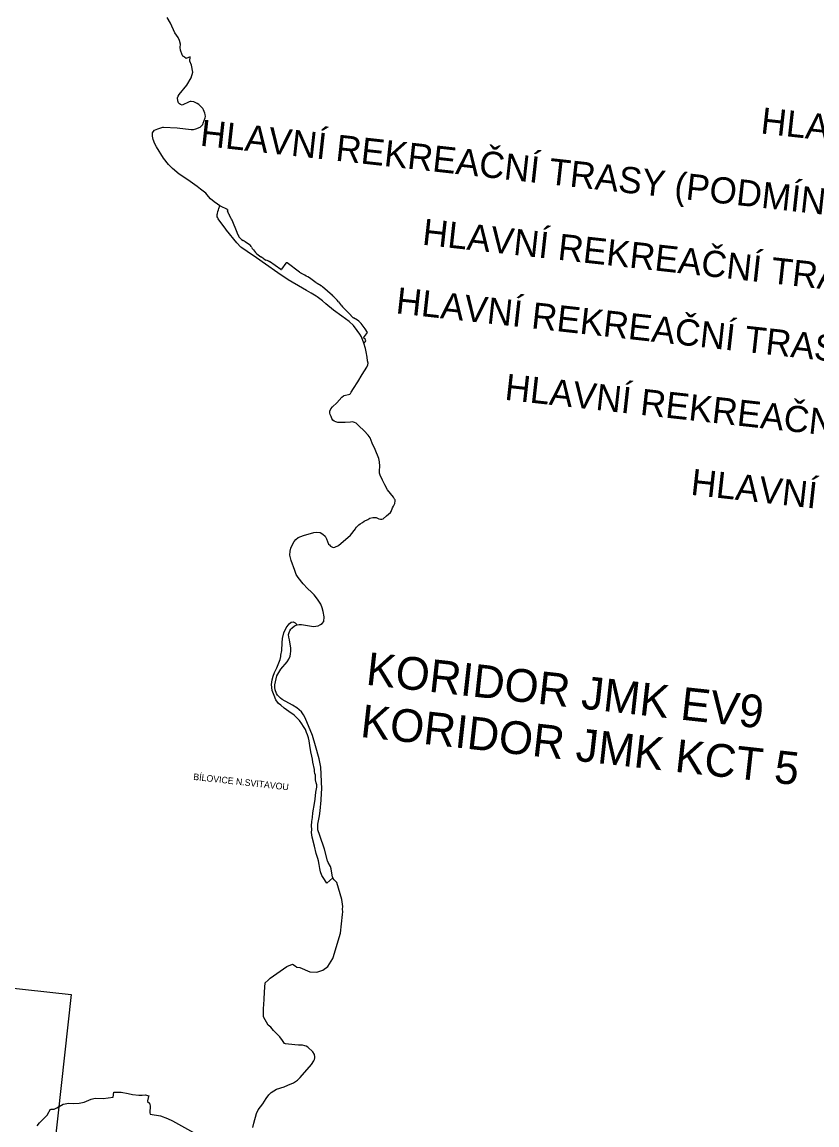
# Model space of a CAD drawing. Extents: x -678204 to -526855, y -1228851 to -1110393.
# Drawn here: x -595642 to -588360, y -1157650 to -1147551 of the extents above; entities that cross this region are included whole.
import ezdxf

# ---------------------------------------------------------------- set-up
doc = ezdxf.new("R2010")
doc.units = 0
for name, color, linetype in [('00_n_cyklo popisy', 7, 'Continuous'), ('00_n_cyklo popisy detaily', 7, 'Continuous'), ('00_n_cyklo prujezdne podminecne rekreacni vedlejsi', 7, 'Continuous'), ('00_n_cyklo prujezdne rekreacni hlavni', 7, 'Continuous'), ('00_n_cyklo studie rekreacni vedlejsi', 7, 'Continuous'), ('00_n_cyklo trasovani rekreacni hlavni', 7, 'Continuous'), ('00_n_cyklo trasovani rekreacni vedlejsi', 7, 'Continuous'), ('00_n_legenda popisy', 7, 'Continuous'), ('_HELP', 7, 'Continuous')]:
    doc.layers.add(name, color=color, linetype=linetype)

msp = doc.modelspace()

# ---------------------------------------------------------------- linework, layer by layer
at = {"layer": '00_n_cyklo prujezdne podminecne rekreacni vedlejsi'}
msp.add_lwpolyline([(-592796, -1155387), (-592849, -1155435), (-592855, -1155427), (-592878, -1155393), (-592894, -1155365), (-592907, -1155332), (-592915, -1155302), (-592920, -1155265), (-592925, -1155231), (-592932, -1155210), (-592947, -1155163), (-592962, -1155097), (-592983, -1155015), (-592990, -1154971), (-592988, -1154944), (-592989, -1154910), (-592987, -1154872), (-592982, -1154835), (-592977, -1154792), (-592962, -1154707), (-592958, -1154667), (-592951, -1154603), (-592940, -1154558), (-592941, -1154535), (-592946, -1154518), (-592952, -1154490), (-592953, -1154466), (-592955, -1154446), (-592960, -1154432), (-592962, -1154414), (-592964, -1154396), (-592978, -1154329), (-592982, -1154301), (-592987, -1154273), (-592995, -1154232), (-593006, -1154175), (-593012, -1154134), (-593018, -1154106), (-593027, -1154079), (-593037, -1154055), (-593046, -1154030), (-593062, -1154001), (-593079, -1153976), (-593099, -1153948), (-593114, -1153931), (-593148, -1153899), (-593198, -1153865), (-593240, -1153834), (-593272, -1153807), (-593291, -1153792), (-593316, -1153756), (-593332, -1153719), (-593349, -1153671), (-593356, -1153618), (-593350, -1153574), (-593341, -1153542), (-593330, -1153508), (-593309, -1153465), (-593278, -1153387), (-593270, -1153359), (-593270, -1153347), (-593263, -1153307), (-593260, -1153234), (-593256, -1153195), (-593243, -1153144), (-593222, -1153097), (-593196, -1153062), (-593177, -1153046), (-593158, -1153043), (-593141, -1153051), (-593132, -1153062), (-593128, -1153074)], dxfattribs=at)
at = {"layer": '00_n_cyklo prujezdne rekreacni hlavni'}
for points in [[(-593529, -1157674), (-593517, -1157635), (-593493, -1157546), (-593479, -1157511), (-593436, -1157456), (-593406, -1157409), (-593380, -1157374), (-593369, -1157361), (-593359, -1157353), (-593312, -1157323), (-593240, -1157300), (-593207, -1157287), (-593155, -1157263), (-593119, -1157240), (-593094, -1157216), (-592991, -1157097), (-592968, -1157063), (-592962, -1157051), (-592959, -1157036), (-592959, -1157026), (-592964, -1157005), (-592979, -1156981), (-593024, -1156939), (-593038, -1156930), (-593051, -1156925), (-593073, -1156920), (-593110, -1156918), (-593144, -1156916), (-593228, -1156908), (-593239, -1156905), (-593255, -1156876), (-593281, -1156844), (-593337, -1156784), (-593364, -1156756), (-593387, -1156736), (-593429, -1156660), (-593430, -1156625), (-593431, -1156588), (-593425, -1156502), (-593422, -1156430), (-593416, -1156350), (-593386, -1156323), (-593369, -1156306), (-593215, -1156199), (-593165, -1156179), (-593141, -1156194), (-593123, -1156204), (-593097, -1156208), (-593004, -1156249), (-592941, -1156251), (-592886, -1156233), (-592841, -1156199), (-592795, -1156127), (-592791, -1156117), (-592724, -1155893), (-592705, -1155724), (-592704, -1155700), (-592706, -1155673), (-592703, -1155650), (-592712, -1155585), (-592759, -1155430), (-592784, -1155405), (-592793, -1155393), (-592799, -1155378), (-592801, -1155363), (-592811, -1155306), (-592817, -1155282), (-592838, -1155246), (-592844, -1155232), (-592872, -1155125), (-592913, -1155001), (-592931, -1154948), (-592933, -1154923), (-592931, -1154896), (-592917, -1154820), (-592910, -1154774), (-592901, -1154675), (-592898, -1154613), (-592896, -1154571), (-592906, -1154373), (-592921, -1154299), (-592953, -1154178), (-592982, -1154083), (-593048, -1153923), (-593063, -1153896), (-593082, -1153868), (-593102, -1153848), (-593124, -1153831), (-593163, -1153807), (-593258, -1153753), (-593273, -1153742), (-593301, -1153715), (-593312, -1153698), (-593322, -1153667), (-593325, -1153643), (-593326, -1153619), (-593308, -1153538), (-593272, -1153478), (-593212, -1153408), (-593197, -1153386), (-593186, -1153356), (-593183, -1153336), (-593179, -1153313), (-593178, -1153285), (-593193, -1153208), (-593199, -1153182), (-593200, -1153158), (-593192, -1153131), (-593189, -1153124), (-593180, -1153110), (-593170, -1153100), (-593147, -1153080), (-593120, -1153071), (-593102, -1153069), (-593082, -1153068), (-592972, -1153085), (-592951, -1153083), (-592929, -1153079), (-592908, -1153069), (-592893, -1153059), (-592878, -1153040), (-592874, -1152997), (-592882, -1152947), (-592891, -1152915), (-592904, -1152881), (-592935, -1152836), (-592966, -1152797), (-592989, -1152771), (-593028, -1152738), (-593068, -1152694), (-593112, -1152638), (-593131, -1152610), (-593144, -1152573), (-593177, -1152482), (-593189, -1152433), (-593187, -1152395), (-593179, -1152368), (-593161, -1152330), (-593149, -1152306), (-593135, -1152288), (-593113, -1152272), (-593062, -1152252), (-592970, -1152225), (-592942, -1152221), (-592910, -1152225), (-592885, -1152240), (-592865, -1152260), (-592852, -1152282), (-592833, -1152332), (-592826, -1152339), (-592815, -1152350), (-592805, -1152357), (-592793, -1152361), (-592776, -1152360), (-592742, -1152343), (-592632, -1152250), (-592588, -1152190), (-592584, -1152184), (-592580, -1152177), (-592576, -1152173), (-592556, -1152156), (-592545, -1152147), (-592524, -1152132), (-592507, -1152122), (-592475, -1152106), (-592455, -1152095), (-592427, -1152087), (-592397, -1152089), (-592372, -1152099), (-592358, -1152103), (-592347, -1152103), (-592335, -1152100), (-592302, -1152072), (-592266, -1152041), (-592260, -1152033), (-592249, -1152000), (-592240, -1151984), (-592231, -1151966), (-592228, -1151961), (-592227, -1151955), (-592224, -1151939), (-592225, -1151927), (-592229, -1151920), (-592240, -1151903), (-592293, -1151833), (-592319, -1151789), (-592341, -1151745), (-592361, -1151699), (-592366, -1151682), (-592368, -1151661), (-592365, -1151617), (-592366, -1151577), (-592373, -1151549), (-592406, -1151466), (-592434, -1151406), (-592453, -1151359), (-592471, -1151335), (-592507, -1151294), (-592556, -1151249), (-592582, -1151225), (-592595, -1151217), (-592615, -1151213), (-592633, -1151214), (-592681, -1151219), (-592748, -1151218), (-592768, -1151213), (-592783, -1151206), (-592794, -1151196), (-592803, -1151181), (-592811, -1151164), (-592818, -1151146), (-592822, -1151132), (-592822, -1151114), (-592813, -1151092), (-592797, -1151074), (-592758, -1151037), (-592712, -1150985), (-592698, -1150975), (-592692, -1150971), (-592640, -1150959), (-592633, -1150951), (-592627, -1150940), (-592606, -1150905), (-592567, -1150844), (-592526, -1150778), (-592484, -1150712), (-592473, -1150690), (-592472, -1150675), (-592476, -1150653), (-592481, -1150620), (-592488, -1150572), (-592496, -1150541), (-592511, -1150491), (-592533, -1150434), (-592546, -1150409), (-592571, -1150374), (-592604, -1150330), (-592645, -1150293), (-592711, -1150244), (-592790, -1150188), (-592859, -1150131), (-592888, -1150104), (-592939, -1150068), (-592947, -1150061), (-592992, -1150035), (-593036, -1150009), (-593073, -1149989), (-593203, -1149910), (-593299, -1149846), (-593412, -1149767), (-593495, -1149711), (-593581, -1149651), (-593627, -1149617), (-593636, -1149611), (-593675, -1149573), (-593768, -1149456), (-593776, -1149447), (-593844, -1149353), (-593849, -1149344), (-593853, -1149335), (-593854, -1149322), (-593853, -1149312), (-593851, -1149303), (-593847, -1149286), (-593842, -1149271), (-593838, -1149259), (-593830, -1149233), (-593883, -1149196), (-593916, -1149170), (-593935, -1149148), (-593958, -1149119), (-593971, -1149108), (-594007, -1149081), (-594036, -1149058), (-594124, -1148996), (-594202, -1148943), (-594263, -1148893), (-594301, -1148854), (-594346, -1148798), (-594409, -1148695), (-594424, -1148667), (-594440, -1148627), (-594445, -1148610), (-594446, -1148596), (-594446, -1148578), (-594446, -1148566), (-594440, -1148555), (-594429, -1148542), (-594399, -1148529), (-594352, -1148514), (-594345, -1148514), (-594221, -1148519), (-594091, -1148536), (-594070, -1148536), (-594049, -1148528), (-594010, -1148514), (-593986, -1148488), (-593984, -1148478), (-593964, -1148429), (-593962, -1148416), (-593963, -1148397), (-593966, -1148384), (-593978, -1148356), (-593986, -1148344), (-594023, -1148305), (-594038, -1148296), (-594069, -1148281), (-594094, -1148279), (-594103, -1148279), (-594110, -1148281), (-594176, -1148312), (-594190, -1148306), (-594198, -1148300), (-594209, -1148290), (-594216, -1148273), (-594219, -1148246), (-594212, -1148230), (-594203, -1148215), (-594131, -1148128), (-594091, -1148062), (-594078, -1148011), (-594090, -1147946), (-594106, -1147910), (-594103, -1147870), (-594137, -1147884), (-594153, -1147874), (-594163, -1147867), (-594169, -1147862), (-594176, -1147851), (-594190, -1147809), (-594193, -1147784), (-594191, -1147754), (-594199, -1147721), (-594213, -1147692), (-594241, -1147651), (-594283, -1147560), (-594313, -1147508)], [(-595503, -1157658), (-595482, -1157631), (-595456, -1157605), (-595411, -1157561), (-595394, -1157528), (-595391, -1157523), (-595383, -1157509), (-595376, -1157506), (-595366, -1157506), (-595358, -1157505), (-595349, -1157504), (-595340, -1157502), (-595322, -1157494), (-595266, -1157459), (-595246, -1157456), (-595217, -1157452), (-595168, -1157454), (-595120, -1157451), (-595074, -1157442), (-595072, -1157441), (-595009, -1157415), (-594973, -1157405), (-594898, -1157409), (-594807, -1157396), (-594802, -1157349), (-594734, -1157351), (-594670, -1157361), (-594631, -1157371), (-594571, -1157378), (-594542, -1157376), (-594514, -1157374), (-594480, -1157383), (-594483, -1157391), (-594491, -1157428), (-594492, -1157435), (-594473, -1157451), (-594467, -1157474), (-594472, -1157540), (-594468, -1157552), (-594374, -1157568), (-594308, -1157591), (-594262, -1157613), (-594071, -1157720)]]:
    msp.add_lwpolyline(points, dxfattribs=at)
at = {"layer": '00_n_cyklo studie rekreacni vedlejsi'}
for p, q in [((-593830, -1149233), (-593874, -1149203)), ((-593759, -1149267), (-593823, -1149236)), ((-593760, -1149269), (-593759, -1149267)), ((-593759, -1149282), (-593760, -1149280)), ((-593726, -1149349), (-593744, -1149316)), ((-593678, -1149464), (-593711, -1149380)), ((-593663, -1149501), (-593678, -1149464)), ((-593558, -1149592), (-593598, -1149565)), ((-593541, -1149610), (-593543, -1149607)), ((-593427, -1149720), (-593454, -1149702)), ((-593395, -1149735), (-593408, -1149730)), ((-593272, -1149817), (-593375, -1149745)), ((-593224, -1149759), (-593264, -1149815)), ((-593101, -1149840), (-593212, -1149757)), ((-593052, -1149868), (-593088, -1149849)), ((-592946, -1149940), (-592997, -1149903)), ((-592903, -1149966), (-592938, -1149946)), ((-592799, -1150054), (-592888, -1149977)), ((-592712, -1150150), (-592741, -1150114)), ((-592642, -1150223), (-592681, -1150184)), ((-592628, -1150239), (-592637, -1150229)), ((-592570, -1150281), (-592604, -1150260)), ((-592500, -1150360), (-592526, -1150323)), ((-592477, -1150393), (-592500, -1150360)), ((-592513, -1150443), (-592477, -1150393)), ((-592500, -1150454), (-592513, -1150443)), ((-592512, -1150488), (-592505, -1150485))]:
    msp.add_line(p, q, dxfattribs=at)
for centre, radius, start, end in [((-593802, -1149191), 50, 235.9697, 244.8885), ((-593746, -1149275), 15, 154.4071, 198.8416), ((-593570, -1149218), 200, 198.8416, 209.3956), ((-593944, -1149472), 250, 21.5195, 29.3956), ((-593570, -1149464), 100, 201.5195, 242.0263), ((-593711, -1149729), 200, 55.3642, 62.0263), ((-593586, -1149633), 50, 31.7453, 55.3642), ((-593286, -1149453), 300, 211.7453, 236.0819), ((-593371, -1149637), 100, 236.0403, 248.3149), ((-593432, -1149828), 100, 55.3439, 68.3149), ((-593217, -1149764), 9, 52.7306, 145.3498), ((-593269, -1149812), 6, 235.3439, 325.3498), ((-593039, -1149759), 102, 232.7306, 241.5449), ((-593290, -1150308), 500, 54.054, 61.5449), ((-592887, -1149859), 100, 234.054, 239.5371), ((-592954, -1150052), 100, 48.9168, 59.5371), ((-593128, -1150431), 500, 39.4165, 48.9168), ((-592326, -1149832), 500, 219.4165, 224.6939), ((-592714, -1150293), 100, 39.8478, 44.6939), ((-592552, -1150175), 100, 219.8478, 238.3022), ((-592649, -1150409), 150, 35.1118, 58.3022), ((-592511, -1150468), 18, 289.6427, 51.4215)]:
    msp.add_arc(centre, radius, start, end, dxfattribs=at)
at = {"layer": '00_n_cyklo trasovani rekreacni hlavni'}
for points in [[(-593529, -1157674), (-593517, -1157635), (-593493, -1157546), (-593479, -1157511), (-593436, -1157456), (-593406, -1157409), (-593380, -1157374), (-593369, -1157361), (-593359, -1157353), (-593312, -1157323), (-593240, -1157300), (-593207, -1157287), (-593155, -1157263), (-593119, -1157240), (-593094, -1157216), (-592991, -1157097), (-592968, -1157063), (-592962, -1157051), (-592959, -1157036), (-592959, -1157026), (-592964, -1157005), (-592979, -1156981), (-593024, -1156939), (-593038, -1156930), (-593051, -1156925), (-593073, -1156920), (-593110, -1156918), (-593144, -1156916), (-593228, -1156908), (-593239, -1156905), (-593255, -1156876), (-593281, -1156844), (-593337, -1156784), (-593364, -1156756), (-593387, -1156736), (-593429, -1156660), (-593430, -1156625), (-593431, -1156588), (-593425, -1156502), (-593422, -1156430), (-593416, -1156350), (-593386, -1156323), (-593369, -1156306), (-593215, -1156199), (-593165, -1156179), (-593141, -1156194), (-593123, -1156204), (-593097, -1156208), (-593004, -1156249), (-592941, -1156251), (-592886, -1156233), (-592841, -1156199), (-592795, -1156127), (-592791, -1156117), (-592724, -1155893), (-592705, -1155724), (-592704, -1155700), (-592706, -1155673), (-592703, -1155650), (-592712, -1155585), (-592759, -1155430), (-592784, -1155405), (-592793, -1155393), (-592799, -1155378), (-592801, -1155363), (-592811, -1155306), (-592817, -1155282), (-592838, -1155246), (-592844, -1155232), (-592872, -1155125), (-592913, -1155001), (-592931, -1154948), (-592933, -1154923), (-592931, -1154896), (-592917, -1154820), (-592910, -1154774), (-592901, -1154675), (-592898, -1154613), (-592896, -1154571), (-592906, -1154373), (-592921, -1154299), (-592953, -1154178), (-592982, -1154083), (-593048, -1153923), (-593063, -1153896), (-593082, -1153868), (-593102, -1153848), (-593124, -1153831), (-593163, -1153807), (-593258, -1153753), (-593273, -1153742), (-593301, -1153715), (-593312, -1153698), (-593322, -1153667), (-593325, -1153643), (-593326, -1153619), (-593308, -1153538), (-593272, -1153478), (-593212, -1153408), (-593197, -1153386), (-593186, -1153356), (-593183, -1153336), (-593179, -1153313), (-593178, -1153285), (-593193, -1153208), (-593199, -1153182), (-593200, -1153158), (-593192, -1153131), (-593189, -1153124), (-593180, -1153110), (-593170, -1153100), (-593147, -1153080), (-593120, -1153071), (-593102, -1153069), (-593082, -1153068), (-592972, -1153085), (-592951, -1153083), (-592929, -1153079), (-592908, -1153069), (-592893, -1153059), (-592878, -1153040), (-592874, -1152997), (-592882, -1152947), (-592891, -1152915), (-592904, -1152881), (-592935, -1152836), (-592966, -1152797), (-592989, -1152771), (-593028, -1152738), (-593068, -1152694), (-593112, -1152638), (-593131, -1152610), (-593144, -1152573), (-593177, -1152482), (-593189, -1152433), (-593187, -1152395), (-593179, -1152368), (-593161, -1152330), (-593149, -1152306), (-593135, -1152288), (-593113, -1152272), (-593062, -1152252), (-592970, -1152225), (-592942, -1152221), (-592910, -1152225), (-592885, -1152240), (-592865, -1152260), (-592852, -1152282), (-592833, -1152332), (-592826, -1152339), (-592815, -1152350), (-592805, -1152357), (-592793, -1152361), (-592776, -1152360), (-592742, -1152343), (-592632, -1152250), (-592588, -1152190), (-592584, -1152184), (-592580, -1152177), (-592576, -1152173), (-592556, -1152156), (-592545, -1152147), (-592524, -1152132), (-592507, -1152122), (-592475, -1152106), (-592455, -1152095), (-592427, -1152087), (-592397, -1152089), (-592372, -1152099), (-592358, -1152103), (-592347, -1152103), (-592335, -1152100), (-592302, -1152072), (-592266, -1152041), (-592260, -1152033), (-592249, -1152000), (-592240, -1151984), (-592231, -1151966), (-592228, -1151961), (-592227, -1151955), (-592224, -1151939), (-592225, -1151927), (-592229, -1151920), (-592240, -1151903), (-592293, -1151833), (-592319, -1151789), (-592341, -1151745), (-592361, -1151699), (-592366, -1151682), (-592368, -1151661), (-592365, -1151617), (-592366, -1151577), (-592373, -1151549), (-592406, -1151466), (-592434, -1151406), (-592453, -1151359), (-592471, -1151335), (-592507, -1151294), (-592556, -1151249), (-592582, -1151225), (-592595, -1151217), (-592615, -1151213), (-592633, -1151214), (-592681, -1151219), (-592748, -1151218), (-592768, -1151213), (-592783, -1151206), (-592794, -1151196), (-592803, -1151181), (-592811, -1151164), (-592818, -1151146), (-592822, -1151132), (-592822, -1151114), (-592813, -1151092), (-592797, -1151074), (-592758, -1151037), (-592712, -1150985), (-592698, -1150975), (-592692, -1150971), (-592640, -1150959), (-592633, -1150951), (-592627, -1150940), (-592606, -1150905), (-592567, -1150844), (-592526, -1150778), (-592484, -1150712), (-592473, -1150690), (-592472, -1150675), (-592476, -1150653), (-592481, -1150620), (-592488, -1150572), (-592496, -1150541), (-592511, -1150491), (-592533, -1150434), (-592546, -1150409), (-592571, -1150374), (-592604, -1150330), (-592645, -1150293), (-592711, -1150244), (-592790, -1150188), (-592859, -1150131), (-592888, -1150104), (-592939, -1150068), (-592947, -1150061), (-592992, -1150035), (-593036, -1150009), (-593073, -1149989), (-593203, -1149910), (-593299, -1149846), (-593412, -1149767), (-593495, -1149711), (-593581, -1149651), (-593627, -1149617), (-593636, -1149611), (-593675, -1149573), (-593768, -1149456), (-593776, -1149447), (-593844, -1149353), (-593849, -1149344), (-593853, -1149335), (-593854, -1149322), (-593853, -1149312), (-593851, -1149303), (-593847, -1149286), (-593842, -1149271), (-593838, -1149259), (-593830, -1149233), (-593883, -1149196), (-593916, -1149170), (-593935, -1149148), (-593958, -1149119), (-593971, -1149108), (-594007, -1149081), (-594036, -1149058), (-594124, -1148996), (-594202, -1148943), (-594263, -1148893), (-594301, -1148854), (-594346, -1148798), (-594409, -1148695), (-594424, -1148667), (-594440, -1148627), (-594445, -1148610), (-594446, -1148596), (-594446, -1148578), (-594446, -1148566), (-594440, -1148555), (-594429, -1148542), (-594399, -1148529), (-594352, -1148514), (-594345, -1148514), (-594221, -1148519), (-594091, -1148536), (-594070, -1148536), (-594049, -1148528), (-594010, -1148514), (-593986, -1148488), (-593984, -1148478), (-593964, -1148429), (-593962, -1148416), (-593963, -1148397), (-593966, -1148384), (-593978, -1148356), (-593986, -1148344), (-594023, -1148305), (-594038, -1148296), (-594069, -1148281), (-594094, -1148279), (-594103, -1148279), (-594110, -1148281), (-594176, -1148312), (-594190, -1148306), (-594198, -1148300), (-594209, -1148290), (-594216, -1148273), (-594219, -1148246), (-594212, -1148230), (-594203, -1148215), (-594131, -1148128), (-594091, -1148062), (-594078, -1148011), (-594090, -1147946), (-594106, -1147910), (-594103, -1147870), (-594137, -1147884), (-594153, -1147874), (-594163, -1147867), (-594169, -1147862), (-594176, -1147851), (-594190, -1147809), (-594193, -1147784), (-594191, -1147754), (-594199, -1147721), (-594213, -1147692), (-594241, -1147651), (-594283, -1147560), (-594313, -1147508)], [(-595503, -1157658), (-595482, -1157631), (-595456, -1157605), (-595411, -1157561), (-595394, -1157528), (-595391, -1157523), (-595383, -1157509), (-595376, -1157506), (-595366, -1157506), (-595358, -1157505), (-595349, -1157504), (-595340, -1157502), (-595322, -1157494), (-595266, -1157459), (-595246, -1157456), (-595217, -1157452), (-595168, -1157454), (-595120, -1157451), (-595074, -1157442), (-595072, -1157441), (-595009, -1157415), (-594973, -1157405), (-594898, -1157409), (-594807, -1157396), (-594802, -1157349), (-594734, -1157351), (-594670, -1157361), (-594631, -1157371), (-594571, -1157378), (-594542, -1157376), (-594514, -1157374), (-594480, -1157383), (-594483, -1157391), (-594491, -1157428), (-594492, -1157435), (-594473, -1157451), (-594467, -1157474), (-594472, -1157540), (-594468, -1157552), (-594374, -1157568), (-594308, -1157591), (-594262, -1157613), (-594071, -1157720)]]:
    msp.add_lwpolyline(points, dxfattribs=at)
at = {"layer": '00_n_cyklo trasovani rekreacni vedlejsi'}
for p, q in [((-593830, -1149233), (-593874, -1149203)), ((-593759, -1149267), (-593823, -1149236)), ((-593760, -1149269), (-593759, -1149267)), ((-593759, -1149282), (-593760, -1149280)), ((-593726, -1149349), (-593744, -1149316)), ((-593678, -1149464), (-593711, -1149380)), ((-593663, -1149501), (-593678, -1149464)), ((-593558, -1149592), (-593598, -1149565)), ((-593541, -1149610), (-593543, -1149607)), ((-593427, -1149720), (-593454, -1149702)), ((-593395, -1149735), (-593408, -1149730)), ((-593272, -1149817), (-593375, -1149745)), ((-593224, -1149759), (-593264, -1149815)), ((-593101, -1149840), (-593212, -1149757)), ((-593052, -1149868), (-593088, -1149849)), ((-592946, -1149940), (-592997, -1149903)), ((-592903, -1149966), (-592938, -1149946)), ((-592799, -1150054), (-592888, -1149977)), ((-592712, -1150150), (-592741, -1150114)), ((-592642, -1150223), (-592681, -1150184)), ((-592628, -1150239), (-592637, -1150229)), ((-592570, -1150281), (-592604, -1150260)), ((-592500, -1150360), (-592526, -1150323)), ((-592477, -1150393), (-592500, -1150360)), ((-592513, -1150443), (-592477, -1150393)), ((-592500, -1150454), (-592513, -1150443)), ((-592512, -1150488), (-592505, -1150485))]:
    msp.add_line(p, q, dxfattribs=at)
msp.add_lwpolyline([(-592796, -1155387), (-592849, -1155435), (-592855, -1155427), (-592878, -1155393), (-592894, -1155365), (-592907, -1155332), (-592915, -1155302), (-592920, -1155265), (-592925, -1155231), (-592932, -1155210), (-592947, -1155163), (-592962, -1155097), (-592983, -1155015), (-592990, -1154971), (-592988, -1154944), (-592989, -1154910), (-592987, -1154872), (-592982, -1154835), (-592977, -1154792), (-592962, -1154707), (-592958, -1154667), (-592951, -1154603), (-592940, -1154558), (-592941, -1154535), (-592946, -1154518), (-592952, -1154490), (-592953, -1154466), (-592955, -1154446), (-592960, -1154432), (-592962, -1154414), (-592964, -1154396), (-592978, -1154329), (-592982, -1154301), (-592987, -1154273), (-592995, -1154232), (-593006, -1154175), (-593012, -1154134), (-593018, -1154106), (-593027, -1154079), (-593037, -1154055), (-593046, -1154030), (-593062, -1154001), (-593079, -1153976), (-593099, -1153948), (-593114, -1153931), (-593148, -1153899), (-593198, -1153865), (-593240, -1153834), (-593272, -1153807), (-593291, -1153792), (-593316, -1153756), (-593332, -1153719), (-593349, -1153671), (-593356, -1153618), (-593350, -1153574), (-593341, -1153542), (-593330, -1153508), (-593309, -1153465), (-593278, -1153387), (-593270, -1153359), (-593270, -1153347), (-593263, -1153307), (-593260, -1153234), (-593256, -1153195), (-593243, -1153144), (-593222, -1153097), (-593196, -1153062), (-593177, -1153046), (-593158, -1153043), (-593141, -1153051), (-593132, -1153062), (-593128, -1153074)], dxfattribs=at)
for centre, radius, start, end in [((-593802, -1149191), 50, 235.9697, 244.8885), ((-593746, -1149275), 15, 154.4071, 198.8416), ((-593570, -1149218), 200, 198.8416, 209.3956), ((-593944, -1149472), 250, 21.5195, 29.3956), ((-593570, -1149464), 100, 201.5195, 242.0263), ((-593711, -1149729), 200, 55.3642, 62.0263), ((-593586, -1149633), 50, 31.7453, 55.3642), ((-593286, -1149453), 300, 211.7453, 236.0819), ((-593371, -1149637), 100, 236.0403, 248.3149), ((-593432, -1149828), 100, 55.3439, 68.3149), ((-593217, -1149764), 9, 52.7306, 145.3498), ((-593269, -1149812), 6, 235.3439, 325.3498), ((-593039, -1149759), 102, 232.7306, 241.5449), ((-593290, -1150308), 500, 54.054, 61.5449), ((-592887, -1149859), 100, 234.054, 239.5371), ((-592954, -1150052), 100, 48.9168, 59.5371), ((-593128, -1150431), 500, 39.4165, 48.9168), ((-592326, -1149832), 500, 219.4165, 224.6939), ((-592714, -1150293), 100, 39.8478, 44.6939), ((-592552, -1150175), 100, 219.8478, 238.3022), ((-592649, -1150409), 150, 35.1118, 58.3022), ((-592511, -1150468), 18, 289.6427, 51.4215)]:
    msp.add_arc(centre, radius, start, end, dxfattribs=at)
at = {"layer": '_HELP'}
msp.add_lwpolyline([(-599907, -1155939), (-595192, -1156457), (-595561, -1159815), (-600276, -1159297)], close=True, dxfattribs=at)

# ---------------------------------------------------------------- texts
at = {"layer": '00_n_cyklo popisy'}
for s, p in [('KORIDOR JMK EV9', (-592499, -1153618)), ('KORIDOR JMK KCT 5', (-592550, -1154096))]:
    msp.add_text(s, height=300, rotation=353.6836, dxfattribs=at).set_placement(p)
at = {"layer": '00_n_cyklo popisy detaily'}
msp.add_text('BÍLOVICE N.SVITAVOU', height=60, rotation=353.6836, dxfattribs=at).set_placement((-594075, -1154490))
at = {"layer": '00_n_legenda popisy'}
for s, p in [('HLAVNÍ REKREAČNÍ TRASY (PRŮJEZDNÉ ÚSEKY) ', (-588882, -1148570)), ('HLAVNÍ REKREAČNÍ TRASY (PODMÍNĚNĚ PRŮJEZDNÉ ÚSEKY K PROVĚŘENÍ) ', (-594017, -1148682)), ('HLAVNÍ REKREAČNÍ TRASY (NEPRŮJEZNÉ ÚSEKY K PROVĚŘENÍ) ', (-591982, -1149589)), ('HLAVNÍ REKREAČNÍ TRASY (PROJEKČNĚ PŘIPRAVOVANÉ ÚSEKY) ', (-592224, -1150217)), ('HLAVNÍ REKREAČNÍ TRASY (STUDIJNĚ PROVĚŘENÉ ÚSEKY) ', (-591227, -1151009)), ('HLAVNÍ REKREAČNÍ TRASY (EXISTUJÍCÍ ZNAČENÍ) ', (-589523, -1151879))]:
    msp.add_text(s, height=240, rotation=353.6836, dxfattribs=at).set_placement(p)

doc.saveas('drawing.dxf')
